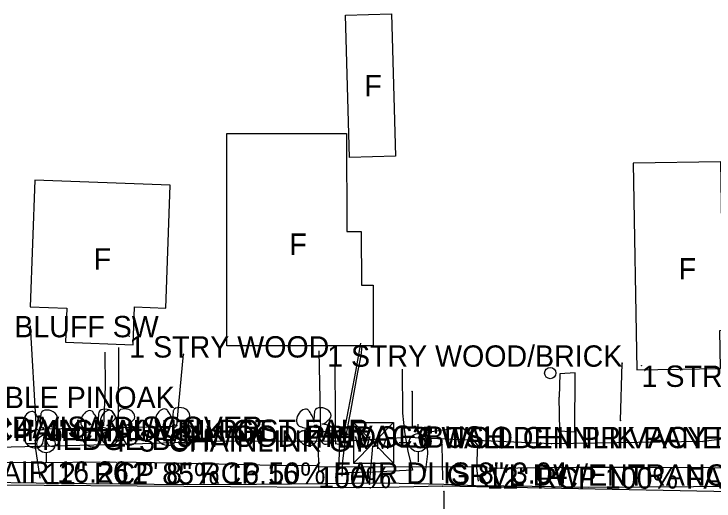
# Model space of a CAD drawing. Extents: x 1304270 to 1306561, y 1876019 to 1876752.
# Drawn here: x 1305136 to 1305299.9, y 1876417.9 to 1876531.9 of the extents above; entities that cross this region are included whole.
import ezdxf

# ---------------------------------------------------------------- set-up
doc = ezdxf.new("R2010")
doc.units = 0
for name, color, linetype in [('S_BUILDING', 7, 'Continuous'), ('S_BUILDING_ANNOT', 7, 'Continuous'), ('S_CURB', 7, 'Continuous'), ('S_DITCHLINE', 7, 'Continuous'), ('S_DRG_PT_SYM', 7, 'Continuous'), ('S_DRIVEWAY', 7, 'Continuous'), ('S_EDGE_CONCRETE', 7, 'Continuous'), ('S_EDGE_PAVEMENT', 7, 'Continuous'), ('S_FENCE', 7, 'Continuous'), ('S_FENCE_ANNOT', 7, 'Continuous'), ('S_FIBER_OPTIC_CABLE', 7, 'Continuous'), ('S_GATE_ANNOT', 7, 'Continuous'), ('S_MSC_PT_SYM', 7, 'Continuous'), ('S_SIDE_DRAIN', 7, 'Continuous'), ('S_SIDE_DRAIN_ANNOT', 7, 'Continuous'), ('S_SIDEWALK', 7, 'Continuous'), ('S_SIGN_ANNOT', 7, 'Continuous'), ('S_STR_PT_SYM', 7, 'Continuous'), ('S_SURVEY_TEXT_ANNOT', 7, 'Continuous'), ('S_TREE', 7, 'Continuous'), ('S_TREE_ANNOT', 7, 'Continuous'), ('S_UTILITY_POLE', 7, 'Continuous'), ('S_UTL_PT_SYM', 7, 'Continuous'), ('S_WATER_UTILITIES', 7, 'Continuous')]:
    doc.layers.add(name, color=color, linetype=linetype)

msp = doc.modelspace()

# ---------------------------------------------------------------- linework, layer by layer
at = {"layer": 'S_BUILDING'}
for points in [[(1305214.58, 1876498.3), (1305213.67, 1876531.59), (1305224.4, 1876531.89), (1305225.31, 1876498.6)], [(1305185.88, 1876454.15), (1305185.83, 1876503.87), (1305213.89, 1876503.9), (1305213.92, 1876480.97), (1305217.35, 1876480.98), (1305217.37, 1876468.41), (1305220.12, 1876468.41), (1305220.14, 1876454.19)], [(1305281, 1876496.94), (1305281.8, 1876448.54), (1305301.42, 1876448.87), (1305301.27, 1876457.78), (1305308.02, 1876457.89), (1305307.85, 1876468.4), (1305301.98, 1876468.31), (1305301.5, 1876497.28)], [(1305172.62, 1876491.8), (1305140.94, 1876492.97), (1305139.84, 1876463.34), (1305148.38, 1876463.03), (1305148.09, 1876455.03), (1305163.93, 1876454.44), (1305164.26, 1876463.29), (1305171.55, 1876463.02)]]:
    msp.add_lwpolyline(points, close=True, dxfattribs=at)
at = {"layer": 'S_CURB'}
msp.add_lwpolyline([(1305213.08, 1876432.59), (1305214.06, 1876437.6), (1305216.05, 1876448.14), (1305217.26, 1876454.82)], dxfattribs=at)
at = {"layer": 'S_DITCHLINE'}
for points in [[(1305143.35, 1876426.88), (1305156.25, 1876427.03)], [(1305160.35, 1876427.06), (1305177.62, 1876426.71), (1305199.99, 1876426.17), (1305206.77, 1876426.26)], [(1305247.21, 1876425.53), (1305267.67, 1876425.8), (1305283.64, 1876425.76), (1305299.6, 1876425.71), (1305312.56, 1876425.61), (1305325.53, 1876425.51)]]:
    msp.add_lwpolyline(points, dxfattribs=at)
at = {"layer": 'S_DRG_PT_SYM'}
for points in [[(1305143.1, 1876426.78), (1305143.1, 1876426.83), (1305143.1, 1876426.78), (1305143.05, 1876426.78), (1305143.1, 1876426.78), (1305143.1, 1876426.73), (1305143.1, 1876426.78), (1305143.15, 1876426.78)], [(1305156.94, 1876427.01), (1305156.94, 1876427.06), (1305156.94, 1876427.01), (1305156.89, 1876427.01), (1305156.94, 1876427.01), (1305156.94, 1876426.96), (1305156.94, 1876427.01), (1305156.99, 1876427.01)], [(1305160, 1876426.88), (1305160, 1876426.93), (1305160, 1876426.88), (1305159.95, 1876426.88), (1305160, 1876426.88), (1305160, 1876426.83), (1305160, 1876426.88), (1305160.05, 1876426.88)], [(1305207.24, 1876425.87), (1305207.24, 1876425.92), (1305207.24, 1876425.87), (1305207.19, 1876425.87), (1305207.24, 1876425.87), (1305207.24, 1876425.82), (1305207.24, 1876425.87), (1305207.29, 1876425.87)], [(1305246.72, 1876425.74), (1305246.72, 1876425.79), (1305246.72, 1876425.74), (1305246.67, 1876425.74), (1305246.72, 1876425.74), (1305246.72, 1876425.69), (1305246.72, 1876425.74), (1305246.77, 1876425.74)]]:
    msp.add_lwpolyline(points, dxfattribs=at)
at = {"layer": 'S_DRIVEWAY'}
for points in [[(1305139.82, 1876458.87), (1305141.19, 1876435.89), (1305141.02, 1876430.51), (1305142.08, 1876423.18)], [(1305212.89, 1876423.63), (1305213.05, 1876427.2), (1305213.61, 1876432.26), (1305214.55, 1876437.32), (1305214.83, 1876438.51), (1305216.56, 1876448.01), (1305217.3, 1876451.89), (1305217.55, 1876454.1)], [(1305226.87, 1876448.69), (1305226.96, 1876438.45), (1305227.43, 1876434.06), (1305228.21, 1876429.51), (1305229.29, 1876425.08), (1305220.31, 1876424.61), (1305213.53, 1876424.45)], [(1305244.77, 1876422.53), (1305244.41, 1876425.53), (1305244.61, 1876430.92), (1305241.14, 1876435.08), (1305232.59, 1876433.87), (1305232.84, 1876428.89), (1305232.33, 1876424.54)]]:
    msp.add_lwpolyline(points, dxfattribs=at)
at = {"layer": 'S_EDGE_CONCRETE'}
for points in [[(1305207.4, 1876424.85), (1305207.35, 1876431.22), (1305207.35, 1876431.3), (1305207.52, 1876431.9), (1305207.57, 1876432.12), (1305207.66, 1876433.1), (1305207.84, 1876433.24), (1305207.72, 1876434.01), (1305207.84, 1876434.22), (1305207.49, 1876453.02)], [(1305211.14, 1876453.06), (1305211.25, 1876434.55), (1305211.29, 1876434.47), (1305211.2, 1876433.61), (1305211.17, 1876433.38), (1305211.2, 1876432.35), (1305211.19, 1876432.03), (1305211.31, 1876431.31), (1305211.24, 1876431.32), (1305212.17, 1876431.18), (1305212.05, 1876425.16)], [(1305207.66, 1876433.1), (1305211.17, 1876433.38)], [(1305207.72, 1876434.01), (1305211.29, 1876434.47)], [(1305207.52, 1876431.9), (1305211.19, 1876432.03)]]:
    msp.add_lwpolyline(points, dxfattribs=at)
at = {"layer": 'S_EDGE_PAVEMENT'}
msp.add_lwpolyline([(1305129.36, 1876422.24), (1305153.05, 1876421.96), (1305176.73, 1876421.68), (1305192.78, 1876421.82), (1305208.83, 1876421.96), (1305222.69, 1876422.09), (1305236.66, 1876421.78), (1305244.11, 1876421.46), (1305257.34, 1876421.3), (1305270.57, 1876421.13), (1305295.07, 1876421.24), (1305319.57, 1876421.34), (1305324.62, 1876421.52), (1305326.39, 1876422.14), (1305337.23, 1876422.2), (1305349.55, 1876421.53), (1305351.84, 1876421.09), (1305367.55, 1876421.04), (1305383.27, 1876420.99)], dxfattribs=at)
at = {"layer": 'S_FENCE'}
for p, q in [((1305174.17, 1876435.53), (1305175.71, 1876452.2)), ((1305278.03, 1876436.7), (1305278.39, 1876450.12)), ((1305229.23, 1876443.5), (1305229.26, 1876435.21))]:
    msp.add_line(p, q, dxfattribs=at)
for points in [[(1305174.17, 1876435.53), (1305175.71, 1876452.2)], [(1305174.17, 1876435.53), (1305175.71, 1876452.2)], [(1305278.03, 1876436.7), (1305278.39, 1876450.12)], [(1305278.03, 1876436.7), (1305278.39, 1876450.12)], [(1305229.23, 1876443.5), (1305229.26, 1876435.21)], [(1305229.23, 1876443.5), (1305229.26, 1876435.21)]]:
    msp.add_lwpolyline(points, dxfattribs=at)
at = {"layer": 'S_FIBER_OPTIC_CABLE'}
for p, q in [((1305317.24, 1876434.23), (1305297.35, 1876431.8)), ((1305185.93, 1876431.87), (1305161.12, 1876431.11)), ((1305212.92, 1876431.8), (1305185.93, 1876431.87)), ((1305228.12, 1876432.7), (1305212.92, 1876431.8)), ((1305261.91, 1876431.26), (1305228.12, 1876432.7)), ((1305297.35, 1876431.8), (1305261.91, 1876431.26)), ((1305161.12, 1876431.11), (1305131.24, 1876430.32))]:
    msp.add_line(p, q, dxfattribs=at)
at = {"layer": 'S_MSC_PT_SYM'}
for points in [[(1305175.71, 1876452.2), (1305175.71, 1876452.25), (1305175.71, 1876452.2), (1305175.66, 1876452.2), (1305175.71, 1876452.2), (1305175.71, 1876452.15), (1305175.71, 1876452.2), (1305175.76, 1876452.2)], [(1305278.39, 1876450.12), (1305278.39, 1876450.17), (1305278.39, 1876450.12), (1305278.34, 1876450.12), (1305278.39, 1876450.12), (1305278.39, 1876450.07), (1305278.39, 1876450.12), (1305278.44, 1876450.12)], [(1305282.96, 1876449.57), (1305282.96, 1876449.62), (1305282.96, 1876449.57), (1305282.91, 1876449.57), (1305282.96, 1876449.57), (1305282.96, 1876449.52), (1305282.96, 1876449.57), (1305283.01, 1876449.57)], [(1305229.23, 1876443.5), (1305229.23, 1876443.55), (1305229.23, 1876443.5), (1305229.18, 1876443.5), (1305229.23, 1876443.5), (1305229.23, 1876443.45), (1305229.23, 1876443.5), (1305229.28, 1876443.5)], [(1305278.03, 1876436.7), (1305278.03, 1876436.75), (1305278.03, 1876436.7), (1305277.98, 1876436.7), (1305278.03, 1876436.7), (1305278.03, 1876436.65), (1305278.03, 1876436.7), (1305278.08, 1876436.7)], [(1305174.17, 1876435.53), (1305174.17, 1876435.58), (1305174.17, 1876435.53), (1305174.12, 1876435.53), (1305174.17, 1876435.53), (1305174.17, 1876435.48), (1305174.17, 1876435.53), (1305174.22, 1876435.53)], [(1305229.26, 1876435.21), (1305229.26, 1876435.26), (1305229.26, 1876435.21), (1305229.21, 1876435.21), (1305229.26, 1876435.21), (1305229.26, 1876435.16), (1305229.26, 1876435.21), (1305229.31, 1876435.21)], [(1305230.44, 1876435.19), (1305230.44, 1876435.24), (1305230.44, 1876435.19), (1305230.39, 1876435.19), (1305230.44, 1876435.19), (1305230.44, 1876435.14), (1305230.44, 1876435.19), (1305230.49, 1876435.19)], [(1305158.5, 1876434.42), (1305158.5, 1876434.47), (1305158.5, 1876434.42), (1305158.45, 1876434.42), (1305158.5, 1876434.42), (1305158.5, 1876434.37), (1305158.5, 1876434.42), (1305158.55, 1876434.42)], [(1305237.36, 1876426.43), (1305237.36, 1876426.48), (1305237.36, 1876426.43), (1305237.31, 1876426.43), (1305237.36, 1876426.43), (1305237.36, 1876426.38), (1305237.36, 1876426.43), (1305237.41, 1876426.43)]]:
    msp.add_lwpolyline(points, dxfattribs=at)
at = {"layer": 'S_SIDE_DRAIN'}
for p, q in [((1305143.1, 1876426.78), (1305126.89, 1876426.87)), ((1305160, 1876426.88), (1305156.94, 1876427.01)), ((1305246.72, 1876425.74), (1305207.24, 1876425.87))]:
    msp.add_line(p, q, dxfattribs=at)
at = {"layer": 'S_SIDEWALK'}
for points in [[(1305157.34, 1876452.74), (1305157.41, 1876444.58), (1305156.99, 1876435.46)], [(1305160.54, 1876435.42), (1305160.58, 1876453.79)], [(1305263.79, 1876434.3), (1305267.33, 1876434.08), (1305267.4, 1876447.83), (1305263.83, 1876447.66), (1305263.65, 1876442.16)], [(1305263.79, 1876434.3), (1305263.65, 1876442.16)]]:
    msp.add_lwpolyline(points, dxfattribs=at)
at = {"layer": 'S_STR_PT_SYM'}
for points in [[(1305163.04, 1876456.44), (1305163.04, 1876456.49), (1305163.04, 1876456.44), (1305162.99, 1876456.44), (1305163.04, 1876456.44), (1305163.04, 1876456.39), (1305163.04, 1876456.44), (1305163.09, 1876456.44)], [(1305209.35, 1876454.29), (1305209.35, 1876454.34), (1305209.35, 1876454.29), (1305209.3, 1876454.29), (1305209.35, 1876454.29), (1305209.35, 1876454.24), (1305209.35, 1876454.29), (1305209.4, 1876454.29)]]:
    msp.add_lwpolyline(points, dxfattribs=at)
at = {"layer": 'S_TREE'}
for p, q in [((1305142.24, 1876435.77), (1305142, 1876436.67)), ((1305155.8, 1876435.99), (1305155.56, 1876436.88)), ((1305160.37, 1876436.06), (1305160.13, 1876436.96)), ((1305173.24, 1876436.37), (1305173, 1876437.26)), ((1305206.3, 1876436.32), (1305206.06, 1876437.21)), ((1305141.59, 1876434.61), (1305140.62, 1876434.39)), ((1305142.61, 1876434.79), (1305156.17, 1876435.01)), ((1305144.19, 1876435.31), (1305144.57, 1876435.47)), ((1305155.15, 1876434.82), (1305154.18, 1876434.61)), ((1305157.75, 1876435.53), (1305158.13, 1876435.69)), ((1305159.72, 1876434.9), (1305158.75, 1876434.68)), ((1305160.74, 1876435.09), (1305173.61, 1876435.39)), ((1305162.32, 1876435.6), (1305162.7, 1876435.77)), ((1305172.59, 1876435.21), (1305171.62, 1876434.99)), ((1305175.19, 1876435.91), (1305175.57, 1876436.07)), ((1305205.65, 1876435.16), (1305204.68, 1876434.94)), ((1305208.25, 1876435.86), (1305208.63, 1876436.02)), ((1305143.13, 1876433.68), (1305143.21, 1876433.24)), ((1305156.69, 1876433.89), (1305156.76, 1876433.45)), ((1305161.26, 1876433.97), (1305161.33, 1876433.53)), ((1305174.13, 1876434.28), (1305174.2, 1876433.84)), ((1305207.19, 1876434.22), (1305207.27, 1876433.79))]:
    msp.add_line(p, q, dxfattribs=at)
for centre in [(1305142.61, 1876434.79), (1305156.17, 1876435.01), (1305160.74, 1876435.09), (1305173.61, 1876435.39), (1305206.67, 1876435.34)]:
    msp.add_circle(centre, 0.341, dxfattribs=at)
for centre, major_axis, ratio, start_param, end_param in [((1305157.83, 1876437.89), (1.89, -0.74), 0.673998, 0, 3.141593), ((1305162.4, 1876437.97), (1.89, -0.74), 0.673998, 0, 3.141593), ((1305170.72, 1876437.41), (-1.03, -1.88), 0.662338, 3.141593, 6.283185), ((1305175.27, 1876438.28), (1.89, -0.74), 0.673998, 0, 3.141593), ((1305203.78, 1876437.36), (-1.03, -1.88), 0.662338, 3.141593, 6.283185), ((1305208.33, 1876438.23), (1.89, -0.74), 0.673998, 0, 3.141593), ((1305139.72, 1876436.81), (-1.03, -1.88), 0.662338, 3.141593, 6.283185), ((1305141.38, 1876437.68), (0.62, -1.01), 0.083512, 0, 3.141593), ((1305142.31, 1876437.1), (-0.07, -1.33), 0.068203, 3.141593, 6.283185), ((1305144.27, 1876437.68), (1.89, -0.74), 0.673998, 0, 3.141593), ((1305153.28, 1876437.02), (-1.03, -1.88), 0.662338, 3.141593, 6.283185), ((1305154.93, 1876437.89), (0.62, -1.01), 0.083512, 0, 3.141593), ((1305155.87, 1876437.31), (-0.07, -1.33), 0.068203, 3.141593, 6.283185), ((1305157.85, 1876437.1), (-1.03, -1.88), 0.662338, 3.141593, 6.283185), ((1305159.5, 1876437.97), (0.62, -1.01), 0.083512, 0, 3.141593), ((1305160.44, 1876437.39), (-0.07, -1.33), 0.068203, 3.141593, 6.283185), ((1305172.37, 1876438.28), (0.62, -1.01), 0.083512, 0, 3.141593), ((1305173.31, 1876437.7), (-0.07, -1.33), 0.068203, 3.141593, 6.283185), ((1305205.44, 1876438.23), (0.62, -1.01), 0.083512, 0, 3.141593), ((1305206.37, 1876437.64), (-0.07, -1.33), 0.068203, 3.141593, 6.283185), ((1305145.37, 1876436.21), (-0.798, -0.73), 0.092159, 0, 3.141593), ((1305158.92, 1876436.42), (-0.798, -0.73), 0.092159, 0, 3.141593), ((1305163.5, 1876436.5), (-0.798, -0.73), 0.092159, 0, 3.141593), ((1305176.37, 1876436.8), (-0.798, -0.73), 0.092159, 0, 3.141593), ((1305209.43, 1876436.75), (-0.798, -0.73), 0.092159, 0, 3.141593), ((1305139.66, 1876434.66), (0.964, -0.267), 0.113563, 3.141593, 6.283185), ((1305140.56, 1876434.17), (1.04, 0.44), 0.002756, 3.141593, 6.283185), ((1305145.15, 1876435.08), (0.96, -0.23), 0.056001, 0, 3.141593), ((1305145.23, 1876432.81), (0.88, 2.05), 0.81717, 3.141593, 6.283185), ((1305153.21, 1876434.87), (0.964, -0.267), 0.113563, 3.141593, 6.283185), ((1305154.11, 1876434.38), (1.04, 0.44), 0.002756, 3.141593, 6.283185), ((1305157.78, 1876434.95), (0.964, -0.267), 0.113563, 3.141593, 6.283185), ((1305158.68, 1876434.46), (1.04, 0.44), 0.002756, 3.141593, 6.283185), ((1305158.71, 1876435.3), (0.96, -0.23), 0.056001, 0, 3.141593), ((1305158.79, 1876433.02), (0.88, 2.05), 0.81717, 3.141593, 6.283185), ((1305163.28, 1876435.37), (0.96, -0.23), 0.056001, 0, 3.141593), ((1305163.36, 1876433.1), (0.88, 2.05), 0.81717, 3.141593, 6.283185), ((1305170.65, 1876435.26), (0.964, -0.267), 0.113563, 3.141593, 6.283185), ((1305171.55, 1876434.76), (1.04, 0.44), 0.002756, 3.141593, 6.283185), ((1305176.15, 1876435.68), (0.96, -0.23), 0.056001, 0, 3.141593), ((1305176.23, 1876433.4), (0.88, 2.05), 0.81717, 3.141593, 6.283185), ((1305203.71, 1876435.21), (0.964, -0.267), 0.113563, 3.141593, 6.283185), ((1305204.61, 1876434.71), (1.04, 0.44), 0.002756, 3.141593, 6.283185), ((1305209.21, 1876435.63), (0.96, -0.23), 0.056001, 0, 3.141593), ((1305209.29, 1876433.35), (0.88, 2.05), 0.81717, 3.141593, 6.283185), ((1305140.63, 1876432.13), (2.07, -0.93), 0.760068, 3.141593, 6.283185), ((1305139.04, 1876433.4), (0.477, 0.328), 0.136309, 0, 3.141593), ((1305142.89, 1876432.51), (0.19, 1.31), 0.114148, 3.141593, 5.822668), ((1305143.46, 1876432.47), (0.254, -0.771), 0.051603, 3.141593, 6.283185), ((1305154.19, 1876432.35), (2.07, -0.93), 0.760068, 3.141593, 6.283185), ((1305152.6, 1876433.61), (0.477, 0.328), 0.136309, 0, 3.141593), ((1305156.45, 1876432.73), (0.19, 1.31), 0.114148, 3.141593, 5.822668), ((1305158.76, 1876432.43), (2.07, -0.93), 0.760068, 3.141593, 6.283185), ((1305157.17, 1876433.69), (0.477, 0.328), 0.136309, 0, 3.141593), ((1305157.02, 1876432.68), (0.254, -0.771), 0.051603, 3.141593, 6.283185), ((1305161.02, 1876432.8), (0.19, 1.31), 0.114148, 3.141593, 5.822668), ((1305161.59, 1876432.76), (0.254, -0.771), 0.051603, 3.141593, 6.283185), ((1305171.63, 1876432.73), (2.07, -0.93), 0.760068, 3.141593, 6.283185), ((1305170.04, 1876433.99), (0.477, 0.328), 0.136309, 0, 3.141593), ((1305173.89, 1876433.11), (0.19, 1.31), 0.114148, 3.141593, 5.822668), ((1305174.46, 1876433.07), (0.254, -0.771), 0.051603, 3.141593, 6.283185), ((1305204.69, 1876432.68), (2.07, -0.93), 0.760068, 3.141593, 6.283185), ((1305203.1, 1876433.94), (0.477, 0.328), 0.136309, 0, 3.141593), ((1305206.95, 1876433.06), (0.19, 1.31), 0.114148, 3.141593, 5.822668), ((1305207.52, 1876433.01), (0.254, -0.771), 0.051603, 3.141593, 6.283185), ((1305144.04, 1876431.23), (-0.321, 0.467), 0.094289, 0, 3.141593), ((1305157.59, 1876431.44), (-0.321, 0.467), 0.094289, 0, 3.141593), ((1305162.16, 1876431.52), (-0.321, 0.467), 0.094289, 0, 3.141593), ((1305175.03, 1876431.83), (-0.321, 0.467), 0.094289, 0, 3.141593), ((1305208.09, 1876431.78), (-0.321, 0.467), 0.094289, 0, 3.141593)]:
    msp.add_ellipse(centre, major_axis=major_axis, ratio=ratio, start_param=start_param, end_param=end_param, dxfattribs=at)
at = {"layer": 'S_UTILITY_POLE'}
for p, q in [((1305143.54, 1876433.38), (1305143.54, 1876435.62)), ((1305230.64, 1876433.61), (1305230.64, 1876435.86)), ((1305141.45, 1876431.24), (1305139.12, 1876431.24)), ((1305228.55, 1876431.48), (1305226.23, 1876431.48)), ((1305143.62, 1876426.83), (1305143.62, 1876429.15)), ((1305230.72, 1876427.06), (1305230.72, 1876429.38))]:
    msp.add_line(p, q, dxfattribs=at)
for centre, radius in [((1305261.56, 1876447.8), 1.31), ((1305143.54, 1876431.27), 2.13), ((1305230.65, 1876431.5), 2.13)]:
    msp.add_circle(centre, radius, dxfattribs=at)
at = {"layer": 'S_UTL_PT_SYM'}
for points in [[(1305185.93, 1876431.87), (1305185.93, 1876431.92), (1305185.93, 1876431.87), (1305185.88, 1876431.87), (1305185.93, 1876431.87), (1305185.93, 1876431.82), (1305185.93, 1876431.87), (1305185.98, 1876431.87)], [(1305212.92, 1876431.8), (1305212.92, 1876431.85), (1305212.92, 1876431.8), (1305212.87, 1876431.8), (1305212.92, 1876431.8), (1305212.92, 1876431.75), (1305212.92, 1876431.8), (1305212.97, 1876431.8)], [(1305228.12, 1876432.7), (1305228.12, 1876432.75), (1305228.12, 1876432.7), (1305228.07, 1876432.7), (1305228.12, 1876432.7), (1305228.12, 1876432.65), (1305228.12, 1876432.7), (1305228.17, 1876432.7)], [(1305261.91, 1876431.26), (1305261.91, 1876431.31), (1305261.91, 1876431.26), (1305261.86, 1876431.26), (1305261.91, 1876431.26), (1305261.91, 1876431.21), (1305261.91, 1876431.26), (1305261.96, 1876431.26)], [(1305297.35, 1876431.8), (1305297.35, 1876431.85), (1305297.35, 1876431.8), (1305297.3, 1876431.8), (1305297.35, 1876431.8), (1305297.35, 1876431.75), (1305297.35, 1876431.8), (1305297.4, 1876431.8)], [(1305161.12, 1876431.11), (1305161.12, 1876431.16), (1305161.12, 1876431.11), (1305161.07, 1876431.11), (1305161.12, 1876431.11), (1305161.12, 1876431.06), (1305161.12, 1876431.11), (1305161.17, 1876431.11)], [(1305220.01, 1876430.67), (1305220.01, 1876430.72), (1305220.01, 1876430.67), (1305219.95, 1876430.67), (1305220.01, 1876430.67), (1305220.01, 1876430.62), (1305220.01, 1876430.67), (1305220.05, 1876430.67)], [(1305236.25, 1876431.05), (1305236.25, 1876431.1), (1305236.25, 1876431.05), (1305236.2, 1876431.05), (1305236.25, 1876431.05), (1305236.25, 1876431), (1305236.25, 1876431.05), (1305236.3, 1876431.05)], [(1305219.3, 1876421.77), (1305219.3, 1876421.82), (1305219.3, 1876421.77), (1305219.25, 1876421.77), (1305219.3, 1876421.77), (1305219.3, 1876421.72), (1305219.3, 1876421.77), (1305219.35, 1876421.77)], [(1305236.39, 1876422.93), (1305236.39, 1876422.98), (1305236.39, 1876422.93), (1305236.34, 1876422.93), (1305236.39, 1876422.93), (1305236.39, 1876422.88), (1305236.39, 1876422.93), (1305236.44, 1876422.93)], [(1305219.44, 1876420.93), (1305219.44, 1876420.98), (1305219.44, 1876420.93), (1305219.39, 1876420.93), (1305219.44, 1876420.93), (1305219.44, 1876420.88), (1305219.44, 1876420.93), (1305219.49, 1876420.93)], [(1305236.41, 1876421.32), (1305236.41, 1876421.37), (1305236.41, 1876421.32), (1305236.36, 1876421.32), (1305236.41, 1876421.32), (1305236.41, 1876421.27), (1305236.41, 1876421.32), (1305236.46, 1876421.32)], [(1305236.69, 1876420.13), (1305236.69, 1876420.18), (1305236.69, 1876420.13), (1305236.64, 1876420.13), (1305236.69, 1876420.13), (1305236.69, 1876420.08), (1305236.69, 1876420.13), (1305236.74, 1876420.13)]]:
    msp.add_lwpolyline(points, dxfattribs=at)
at = {"layer": 'S_WATER_UTILITIES'}
for p, q in [((1305215.55, 1876436.24), (1305224.89, 1876436.24)), ((1305215.55, 1876436.24), (1305215.55, 1876426.75)), ((1305215.55, 1876436.24), (1305224.89, 1876426.75)), ((1305224.89, 1876436.24), (1305215.55, 1876426.75)), ((1305224.89, 1876436.24), (1305224.89, 1876426.75)), ((1305219.3, 1876421.77), (1305220.01, 1876430.67)), ((1305236.39, 1876422.93), (1305236.25, 1876431.05)), ((1305215.55, 1876426.75), (1305224.89, 1876426.75)), ((1305219.44, 1876420.93), (1305124.9, 1876421.59)), ((1305236.41, 1876421.32), (1305219.44, 1876420.93)), ((1305316.94, 1876419.74), (1305236.41, 1876421.32)), ((1305236.69, 1876420.13), (1305236.52, 1876389.99))]:
    msp.add_line(p, q, dxfattribs=at)

# ---------------------------------------------------------------- texts
at = {"layer": 'S_BUILDING_ANNOT'}
for s, p in [('F', (1305218.05, 1876512.6)), ('F', (1305200.49, 1876475.49)), ('F', (1305154.71, 1876472.03)), ('F', (1305291.62, 1876469.72)), ('1 STRY BRICK/WOOD PINE BLUFF SW', (1305047.7, 1876456.19)), ('1 STRY WOOD', (1305163.04, 1876451.44)), ('1 STRY WOOD/BRICK', (1305209.35, 1876449.29))]:
    msp.add_text(s, height=5, dxfattribs=at).set_placement(p)
at = {"layer": 'S_FENCE_ANNOT'}
for s, p in [("5' CHAINLINK/MTL POST FAIR", (1305124.23, 1876431.91)), ("3' WOOD PRIVACY", (1305174.17, 1876430.53)), ("3' WOODEN PRIVACY FE", (1305229.26, 1876430.21)), ("6' TALL CHINLIK PANEL FE 10'", (1305230.44, 1876430.19))]:
    msp.add_text(s, height=5, dxfattribs=at).set_placement(p)
at = {"layer": 'S_GATE_ANNOT'}
for s, p in [("4' 4' CHAINLINK GT", (1305135.95, 1876431.85)), ("4' 3' CHAINLINK GT", (1305158.5, 1876429.42))]:
    msp.add_text(s, height=5, dxfattribs=at).set_placement(p)
at = {"layer": 'S_SIDE_DRAIN_ANNOT'}
for s, p in [('12" RCP 45% FAIR 16.26', (1305086.22, 1876422.13)), ('12" RCP 85% 16.16', (1305143.1, 1876421.78)), ('12" 8" RCP 50% FAIR DI IS 8" 3.04', (1305160, 1876421.88)), ('100%', (1305207.24, 1876420.87)), ('12" RCP 100% FAIR 39.48', (1305246.72, 1876420.74))]:
    msp.add_text(s, height=5, dxfattribs=at).set_placement(p)
at = {"layer": 'S_SIGN_ANNOT'}
msp.add_text("3.5' MTL MASTERCARD/VISA/DISCOVER", height=5, dxfattribs=at).set_placement((1305065.91, 1876432.62))
at = {"layer": 'S_SURVEY_TEXT_ANNOT'}
for s, p in [('1 STRY WOOD ABANDON BU/HOME', (1305282.96, 1876444.57)), ('GRVL DW/ENTRANCE TO NOWHE', (1305237.36, 1876421.43))]:
    msp.add_text(s, height=5, dxfattribs=at).set_placement(p)
at = {"layer": 'S_TREE_ANNOT'}
for s, p in [('18" DOUBLE PINOAK', (1305107.37, 1876439.6)), ('HEDGE BSH', (1305142.61, 1876429.79)), ('HEDGE BUSH', (1305206.67, 1876430.34))]:
    msp.add_text(s, height=5, dxfattribs=at).set_placement(p)
at = {"layer": 'S_WATER_UTILITIES'}
msp.add_text('W M', height=3, rotation=360, dxfattribs=at).set_placement((1305215.75, 1876430.01))

doc.saveas('drawing.dxf')
